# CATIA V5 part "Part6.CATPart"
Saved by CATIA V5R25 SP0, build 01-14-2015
Part number: Part6
Bounding box of the stored display mesh (mm): x -8 to 8, y -2.5 to 2.5, z -2.462 to 2.462
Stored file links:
  D:\1kinematik uygulama-1-03112025\Part6.CATPart
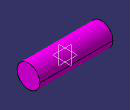
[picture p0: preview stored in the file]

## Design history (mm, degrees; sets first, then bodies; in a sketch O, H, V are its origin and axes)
Body1 (main body)
  Sketch1 on yz-plane, origin (0, 0, 0), H (0, 1, 0), V (0, 0, 1)
    circle A1 centre (0, 0) radius 2.5
    radius A1 = 2.5
  Pad1: profile Sketch1, direction (1, 0, 0), length 8, mirrored extent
